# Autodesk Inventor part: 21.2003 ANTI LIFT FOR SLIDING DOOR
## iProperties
Created: 2007-05
Part Number: 21.2003 ANTI LIFT FOR SLIDING DOOR
Document SubType Name: Modeling
Designer: Andy Moles
Material: UHMW, Black
Mass: 5.14406 g
Surface Area: 23.5238 cm^2
Volume: 5.4724 cm^3
Density: 0.94 g/cm^3
Description: SLIDE BAR 8 L = .787"
Author: Andy Moles
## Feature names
1. Extrusion1
